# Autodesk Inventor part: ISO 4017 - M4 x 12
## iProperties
Created: 2006-11
Part Number: ISO 4017 - M4 x 12
Material: Stahl, weich, unlegiert
Description: Sechskantschraube
Vendor: Autodesk Inc.
Document SubType Name: Modeling
Standard: ISO 4017
Designer: Schmidt
Standards Organization: ISO
Language: de-DE
Size Designation: M4 x 12
Categories: <MemberInstance Version="R10.0.0"><Categories><Category DisplayName="Schrauben" InternalName="e4da775c-781d-43d5-af7c-5136215cf5a6" Mnemonic="FSTN"><Category Di
Density: 7.86 g/cm^3
Author: Schmidt
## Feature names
1. Körper [Revolution]
2. Kopf [Extrusion]
3. Fase1 [Revolution]
4. Fase2 [Chamfer]
